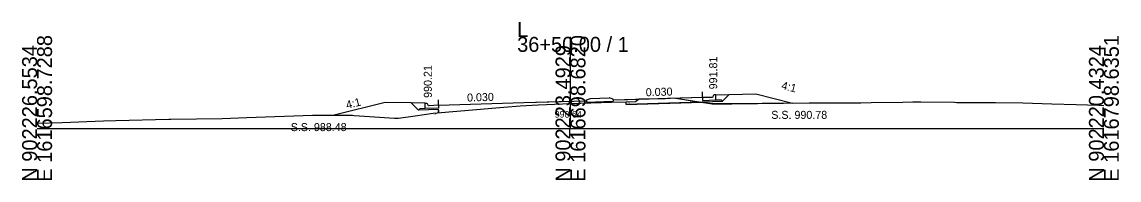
# Model space of a CAD drawing. Extents: x 1009 to 7438, y -1586 to 7964.
# Drawn here: x 3032.1 to 3237.7, y 4414 to 4443.7 of the extents above; entities that cross this region are included whole.
import ezdxf

# ---------------------------------------------------------------- set-up
doc = ezdxf.new("R2010")
doc.units = 0
for name, color, linetype in [('Exist Cross Section Cell', 7, 'Continuous'), ('Exist XS Center Line Elevation Label', 7, 'Continuous'), ('Exist XS Ground Line', 7, 'Continuous'), ('Prop XS Dump Level', 7, 'Continuous'), ('Prop XS Earthwork Shape', 7, 'Continuous'), ('Prop XS EOT Tick Mark', 7, 'Continuous'), ('Prop XS Finish Grade', 7, 'Continuous'), ('Prop XS Finish Grade CurbGutter', 7, 'Continuous'), ('Prop XS Finish Grade Earthwork', 7, 'Continuous'), ('Prop XS Finish Grade Pavement', 7, 'Continuous'), ('Prop XS Hydro Elevations', 7, 'Continuous'), ('Prop XS Pvmt Edge Slope', 7, 'Continuous'), ('Prop XS SE Text', 7, 'Continuous'), ('Prop XS Side Slope Text', 7, 'Continuous'), ('Prop XS SS Elevation Text', 7, 'Continuous'), ('Prop XS Subgrade CurbGutter', 7, 'Continuous'), ('Prop XS Subgrade Earthwork', 7, 'Continuous')]:
    doc.layers.add(name, color=color, linetype=linetype)

msp = doc.modelspace()

# ---------------------------------------------------------------- linework, layer by layer
at = {"layer": 'Exist Cross Section Cell'}
for p, q in [((3134.89, 4423.73), (3134.89, 4440.87)), ((3034.89, 4423.73), (3134.89, 4423.73)), ((3134.89, 4423.73), (3234.89, 4423.73))]:
    msp.add_line(p, q, dxfattribs=at)
at = {"layer": 'Exist XS Ground Line'}
for p, q in [((3130.41, 4428.22), (3134.89, 4428.37)), ((3134.89, 4428.37), (3142.6, 4428.62)), ((3142.6, 4428.62), (3145.34, 4428.7)), ((3145.34, 4428.7), (3147.09, 4428.74)), ((3147.09, 4428.74), (3147.77, 4429.26)), ((3147.77, 4429.26), (3151.92, 4429.34)), ((3151.92, 4429.34), (3152.7, 4429.35)), ((3152.7, 4429.35), (3153.08, 4429.38)), ((3153.08, 4429.38), (3154.21, 4429.44)), ((3154.21, 4429.44), (3161.46, 4428.31)), ((3165.15, 4428.31), (3179.65, 4428.52)), ((3179.65, 4428.52), (3183.83, 4428.54)), ((3183.83, 4428.54), (3189.31, 4428.5)), ((3189.31, 4428.5), (3191.26, 4428.57)), ((3191.26, 4428.57), (3197.22, 4428.66)), ((3197.22, 4428.66), (3199.08, 4428.68)), ((3199.08, 4428.68), (3200.54, 4428.67)), ((3200.54, 4428.67), (3206.86, 4428.62)), ((3206.86, 4428.62), (3207.31, 4428.59)), ((3207.31, 4428.59), (3207.83, 4428.59)), ((3207.83, 4428.59), (3214.55, 4428.55)), ((3214.55, 4428.55), (3219.67, 4428.52)), ((3219.67, 4428.52), (3225.11, 4428.35)), ((3225.11, 4428.35), (3229.67, 4428.2)), ((3105.79, 4426.05), (3109.17, 4426.55)), ((3109.17, 4426.55), (3109.91, 4426.66)), ((3109.91, 4426.66), (3117.25, 4427.29)), ((3117.25, 4427.29), (3120.89, 4427.6)), ((3120.89, 4427.6), (3122.39, 4427.72)), ((3122.39, 4427.72), (3125.48, 4427.98)), ((3125.48, 4427.98), (3128.8, 4428.14)), ((3128.8, 4428.14), (3130.41, 4428.22)), ((3161.46, 4428.31), (3165.15, 4428.31)), ((3229.67, 4428.2), (3233.96, 4428.07)), ((3233.96, 4428.07), (3234.89, 4428.03)), ((3034.89, 4424.71), (3039.58, 4424.85)), ((3039.58, 4424.85), (3047.31, 4425.11)), ((3047.31, 4425.11), (3049.65, 4425.18)), ((3049.65, 4425.18), (3059.59, 4425.42)), ((3059.59, 4425.42), (3059.97, 4425.43)), ((3059.97, 4425.43), (3069.59, 4425.57)), ((3069.59, 4425.57), (3074.19, 4425.75)), ((3074.19, 4425.75), (3086.51, 4426.22)), ((3086.51, 4426.22), (3087.39, 4426.22)), ((3087.39, 4426.22), (3091.35, 4426.21)), ((3091.35, 4426.21), (3094.05, 4426.17)), ((3094.05, 4426.17), (3094.36, 4426.16)), ((3094.36, 4426.16), (3095.34, 4426.09)), ((3095.34, 4426.09), (3101.9, 4425.62)), ((3101.9, 4425.62), (3102.65, 4425.62)), ((3102.65, 4425.62), (3105.79, 4426.05))]:
    msp.add_line(p, q, dxfattribs=at)
at = {"layer": 'Prop XS Dump Level'}
for p, q in [((3110.14, 4428.08), (3126.14, 4428.56)), ((3110.14, 4428.08), (3126.14, 4428.56)), ((3126.14, 4428.56), (3134.89, 4428.82)), ((3126.14, 4428.56), (3134.89, 4428.82)), ((3143.64, 4429.08), (3159.64, 4429.56)), ((3143.64, 4429.08), (3159.64, 4429.56))]:
    msp.add_line(p, q, dxfattribs=at)
at = {"layer": 'Prop XS Earthwork Shape'}
for points in [[(3109.91, 4426.66), (3110.14, 4426.68), (3110.14, 4427.16), (3110.14, 4427.25), (3106.39, 4427.14), (3105.04, 4428.49), (3100.14, 4428.6), (3090.59, 4426.21), (3091.35, 4426.21), (3094.05, 4426.17), (3094.36, 4426.16), (3095.34, 4426.09), (3101.9, 4425.62), (3102.65, 4425.62), (3105.79, 4426.05), (3109.17, 4426.55)], [(3152.7, 4429.35), (3153.08, 4429.38), (3154.21, 4429.44), (3159.35, 4428.64), (3145.35, 4428.22), (3145.35, 4428.7), (3147.09, 4428.74), (3147.77, 4429.26), (3151.92, 4429.34)], [(3169.64, 4430.2), (3176.54, 4428.48), (3165.15, 4428.31), (3161.46, 4428.31), (3159.35, 4428.64), (3159.64, 4428.65), (3159.64, 4428.73), (3163.39, 4428.85), (3164.64, 4430.1)]]:
    msp.add_lwpolyline(points, close=True, dxfattribs=at)
at = {"layer": 'Prop XS EOT Tick Mark'}
for p, q in [((3159.64, 4429.56), (3159.64, 4430.56)), ((3110.14, 4428.08), (3110.14, 4429.08))]:
    msp.add_line(p, q, dxfattribs=at)
at = {"layer": 'Prop XS Finish Grade'}
for p, q in [((3107.64, 4428.44), (3105.04, 4428.49)), ((3162.14, 4430.04), (3164.64, 4430.1))]:
    msp.add_line(p, q, dxfattribs=at)
at = {"layer": 'Prop XS Finish Grade CurbGutter'}
for p, q in [((3107.64, 4428.44), (3107.89, 4428.44)), ((3107.89, 4428.44), (3108.02, 4428.41)), ((3108.11, 4428.32), (3108.02, 4428.41)), ((3137.89, 4429.08), (3138.64, 4429.33)), ((3137.89, 4428.91), (3137.89, 4429.08)), ((3138.64, 4429.33), (3142.14, 4429.48)), ((3142.89, 4429.23), (3142.14, 4429.48)), ((3142.89, 4429.06), (3142.89, 4429.23)), ((3159.64, 4429.56), (3161.39, 4429.55)), ((3161.39, 4429.55), (3161.52, 4429.57)), ((3161.52, 4429.57), (3161.61, 4429.66)), ((3161.61, 4429.66), (3161.68, 4429.91)), ((3161.68, 4429.91), (3161.77, 4430)), ((3161.89, 4430.04), (3161.77, 4430)), ((3162.14, 4430.04), (3161.89, 4430.04)), ((3108.18, 4428.07), (3108.11, 4428.32)), ((3108.27, 4427.98), (3108.18, 4428.07)), ((3108.39, 4427.96), (3108.27, 4427.98)), ((3110.14, 4428.08), (3108.39, 4427.96))]:
    msp.add_line(p, q, dxfattribs=at)
at = {"layer": 'Prop XS Finish Grade Earthwork'}
for p, q in [((3100.14, 4428.6), (3090.59, 4426.21)), ((3105.04, 4428.49), (3100.14, 4428.6)), ((3164.64, 4430.1), (3169.64, 4430.2)), ((3169.64, 4430.2), (3176.54, 4428.48))]:
    msp.add_line(p, q, dxfattribs=at)
at = {"layer": 'Prop XS Finish Grade Pavement'}
for p, q in [((3110.14, 4428.08), (3126.14, 4428.56)), ((3126.14, 4428.56), (3137.89, 4428.91)), ((3142.89, 4429.06), (3159.64, 4429.56))]:
    msp.add_line(p, q, dxfattribs=at)
at = {"layer": 'Prop XS Pvmt Edge Slope'}
for p, q in [((3162.14, 4429.06), (3163.14, 4429.09)), ((3163.14, 4429.09), (3163.39, 4428.85)), ((3106.64, 4427.39), (3106.39, 4427.14)), ((3107.64, 4427.42), (3106.64, 4427.39))]:
    msp.add_line(p, q, dxfattribs=at)
at = {"layer": 'Prop XS Subgrade CurbGutter'}
for p, q in [((3107.64, 4427.42), (3107.64, 4428.44)), ((3137.89, 4428.91), (3137.89, 4428.66)), ((3137.89, 4428.66), (3142.89, 4428.81)), ((3142.89, 4429.06), (3142.89, 4428.81)), ((3159.64, 4429.56), (3159.64, 4428.98)), ((3159.64, 4428.98), (3162.14, 4429.06)), ((3162.14, 4429.06), (3162.14, 4430.04)), ((3110.14, 4427.5), (3107.64, 4427.42)), ((3110.14, 4428.08), (3110.14, 4427.5))]:
    msp.add_line(p, q, dxfattribs=at)
at = {"layer": 'Prop XS Subgrade Earthwork'}
for p, q in [((3106.39, 4427.14), (3105.04, 4428.49)), ((3145.35, 4428.22), (3145.35, 4428.7)), ((3145.35, 4428.22), (3145.35, 4428.7)), ((3145.35, 4428.22), (3159.64, 4428.65)), ((3159.64, 4428.73), (3163.39, 4428.85)), ((3159.64, 4428.65), (3159.64, 4428.73)), ((3163.39, 4428.85), (3164.64, 4430.1)), ((3110.14, 4427.25), (3106.39, 4427.14)), ((3110.14, 4427.16), (3110.14, 4427.25)), ((3110.14, 4427.16), (3110.14, 4426.68))]:
    msp.add_line(p, q, dxfattribs=at)

# ---------------------------------------------------------------- texts
at = {"layer": 'Exist Cross Section Cell'}
for s, p in [('L', (3124.89, 4440.87)), ('36+50.00 / 1', (3124.89, 4438.07))]:
    msp.add_text(s, height=2.8, dxfattribs=at).set_placement(p)
for s, p in [('E 1616598.7288', (3037.69, 4413.73)), ('E 1616698.6820', (3137.69, 4413.73)), ('E 1616798.6351', (3237.69, 4413.73)), ('N 902226.5534', (3034.89, 4413.73)), ('N 902223.4929', (3134.89, 4413.73)), ('N 902220.4324', (3234.89, 4413.73))]:
    msp.add_text(s, height=2.8, rotation=90, dxfattribs=at).set_placement(p)
at = {"layer": 'Exist XS Center Line Elevation Label'}
msp.add_text('990.64', height=1.25, dxfattribs=at).set_placement((3131.91, 4425.74))
at = {"layer": 'Prop XS Dump Level'}
for p in [(3145.35, 4428.4), (3145.35, 4428.4), (3145.35, 4428.4), (3109.18, 4426.26)]:
    msp.add_text('Eop', height=0.3, dxfattribs=at).set_placement(p)
at = {"layer": 'Prop XS Hydro Elevations'}
for s, p in [('991.81', (3162.39, 4431.04)), ('990.21', (3108.89, 4429.44))]:
    msp.add_text(s, height=1.5, rotation=90, dxfattribs=at).set_placement(p)
at = {"layer": 'Prop XS SE Text'}
for p in [(3115.52, 4428.74), (3149.02, 4429.74)]:
    msp.add_text('0.030', height=1.5, rotation=1.7184, dxfattribs=at).set_placement(p)
at = {"layer": 'Prop XS Side Slope Text'}
for rotation, p in [(345.9638, (3174.33, 4431.12)), (14.0362, (3093, 4427.36))]:
    msp.add_text('4:1', height=1.5, rotation=rotation, dxfattribs=at).set_placement(p)
at = {"layer": 'Prop XS SS Elevation Text'}
for s, p in [('S.S. 990.78', (3172.53, 4425.51)), ('S.S. 988.48', (3082.44, 4423.21))]:
    msp.add_text(s, height=1.5, dxfattribs=at).set_placement(p)

doc.saveas('drawing.dxf')
